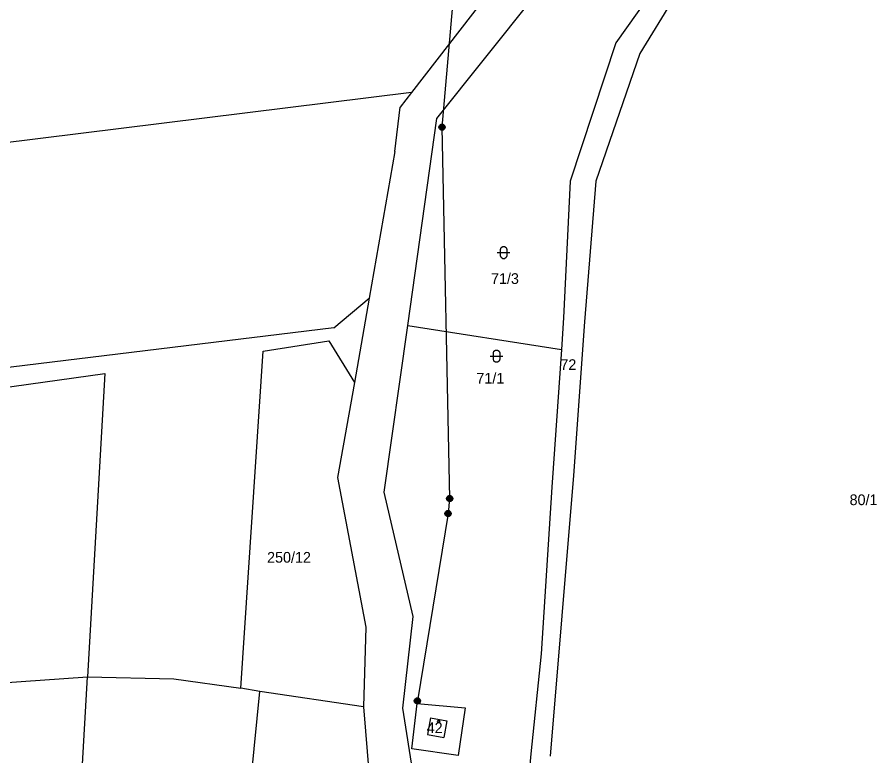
# Model space of a CAD drawing. Extents: x -852001 to -842497, y -1063614 to -1052182.
# Drawn here: x -844444 to -844307.7, y -1061323.1 to -1061205.9 of the extents above; entities that cross this region are included whole.
import ezdxf

# ---------------------------------------------------------------- set-up
doc = ezdxf.new("R2010")
doc.units = 0
for name, color, linetype in [('Default', 7, 'Continuous'), ('KN_HRANICE', 7, 'Continuous'), ('KN_KULTURY', 7, 'Continuous'), ('KN_PARCELY', 7, 'Continuous'), ('KN_SLUCKY', 7, 'Continuous'), ('KN_VEDENI', 7, 'Continuous')]:
    doc.layers.add(name, color=color, linetype=linetype)

# ---------------------------------------------------------------- blocks, each defined once
blk = doc.blocks.new('316')
at = {"layer": 'Default'}
for points in [[(-0.5, 1.5), (-0.4, 1.79), (-0.15, 1.97), (0.16, 1.97), (0.41, 1.79), (0.51, 1.5), (0.51, 0.5), (0.41, 0.21), (0.16, 0.03), (-0.15, 0.03), (-0.4, 0.21), (-0.5, 0.5), (-0.5, 1.5)], [(-1, 1), (0.27, 1), (1, 1)]]:
    blk.add_lwpolyline(points, dxfattribs=at)
blk = doc.blocks.new('402')
at = {"layer": 'Default'}
blk.add_lwpolyline([(0.09, 0.15), (0.18, 0), (0.09, -0.15), (-0.09, -0.15), (-0.18, 0), (-0.09, 0.15), (0.09, 0.15)], dxfattribs=at)
blk = doc.blocks.new('601')
at = {"layer": 'Default'}
blk.add_lwpolyline([(-0.15, 0.48), (0.16, 0.48), (0.41, 0.3), (0.51, 0.01), (0.41, -0.28), (0.16, -0.46), (-0.15, -0.46), (-0.4, -0.28), (-0.5, 0.01), (-0.4, 0.3), (-0.15, 0.48), (-0.12, 0.44), (0.12, 0.44), (0.28, 0.36), (-0.28, 0.36), (-0.36, 0.28), (0.36, 0.28), (0.36, 0.2), (-0.36, 0.2), (-0.4, 0.12), (0.4, 0.12), (0.44, 0.04), (-0.44, 0.04), (-0.44, -0.04), (0.44, -0.04), (0.41, -0.12), (-0.4, -0.12), (-0.39, -0.2), (0.42, -0.2), (0.37, -0.28), (-0.35, -0.28), (-0.27, -0.36), (0.29, -0.36), (0.18, -0.44), (-0.16, -0.44)], dxfattribs=at)

msp = doc.modelspace()

# ---------------------------------------------------------------- linework, layer by layer
at = {"layer": 'KN_HRANICE'}
for p, q in [((-844377.45, -1061221.98), (-844351.54, -1061189.47)), ((-844332.94, -1061191.52), (-844345.28, -1061211.64)), ((-844338.18, -1061194.58), (-844349.09, -1061209.93)), ((-844363.83, -1061194.99), (-844381.5, -1061217.84)), ((-844349.09, -1061209.93), (-844356.33, -1061231.92)), ((-844345.28, -1061211.64), (-844352.26, -1061231.88)), ((-844381.5, -1061217.84), (-844523.56, -1061235.4)), ((-844381.5, -1061217.84), (-844383.3, -1061220.16)), ((-844384.13, -1061227.2), (-844383.3, -1061220.16)), ((-844382.08, -1061254.79), (-844377.45, -1061221.98)), ((-844384.13, -1061227.2), (-844388.18, -1061250.45)), ((-844356.33, -1061231.92), (-844357.35, -1061253.58)), ((-844352.26, -1061231.88), (-844354.02, -1061254.23)), ((-844393.8, -1061255.17), (-844388.18, -1061250.45)), ((-844388.18, -1061250.45), (-844390.51, -1061263.85)), ((-844357.35, -1061253.58), (-844357.7, -1061258.58)), ((-844354.02, -1061254.23), (-844355.8, -1061278.6)), ((-844393.8, -1061255.17), (-844522.5, -1061270.83)), ((-844385.82, -1061281.23), (-844382.08, -1061254.79)), ((-844382.08, -1061254.79), (-844357.7, -1061258.58)), ((-844405.01, -1061258.87), (-844394.6, -1061257.22)), ((-844394.6, -1061257.22), (-844390.51, -1061263.85)), ((-844357.7, -1061258.58), (-844359.23, -1061280.44)), ((-844408.56, -1061312.3), (-844405.01, -1061258.87)), ((-844468.71, -1061267.83), (-844430.13, -1061262.42)), ((-844430.13, -1061262.42), (-844432.89, -1061310.51)), ((-844390.51, -1061263.85), (-844393.23, -1061278.9)), ((-844393.23, -1061278.9), (-844388.72, -1061302.67)), ((-844355.8, -1061278.6), (-844359.49, -1061323.11)), ((-844359.23, -1061280.44), (-844360.93, -1061306.9)), ((-844381.2, -1061300.98), (-844385.82, -1061281.23)), ((-844382.88, -1061315.51), (-844381.2, -1061300.98)), ((-844388.72, -1061302.67), (-844389.08, -1061315.26)), ((-844360.93, -1061306.9), (-844362.55, -1061322.76)), ((-844437.76, -1061395.7), (-844432.89, -1061310.51)), ((-844432.89, -1061310.51), (-844419.21, -1061310.86)), ((-844419.21, -1061310.86), (-844408.56, -1061312.3)), ((-844405.53, -1061312.84), (-844408.56, -1061312.3)), ((-844408.43, -1061341.94), (-844405.53, -1061312.84)), ((-844389.08, -1061315.26), (-844405.53, -1061312.84)), ((-844381.43, -1061321.93), (-844380.57, -1061314.74)), ((-844380.57, -1061314.74), (-844372.96, -1061315.44)), ((-844389.08, -1061315.26), (-844386.69, -1061344.57)), ((-844377.08, -1061352.12), (-844382.88, -1061315.51)), ((-844372.96, -1061315.44), (-844374.09, -1061323)), ((-844374.09, -1061323), (-844381.43, -1061321.93)), ((-844362.55, -1061322.76), (-844366.12, -1061360.65))]:
    msp.add_line(p, q, dxfattribs=at)
at = {"layer": 'KN_SLUCKY'}
for p, q in [((-844471.31, -1061313.26), (-844432.89, -1061310.51)), ((-844378.47, -1061317.03), (-844378.94, -1061319.66)), ((-844378.47, -1061317.03), (-844375.89, -1061317.52)), ((-844375.89, -1061317.52), (-844376.38, -1061320.13)), ((-844378.94, -1061319.66), (-844376.38, -1061320.13))]:
    msp.add_line(p, q, dxfattribs=at)
at = {"layer": 'KN_VEDENI'}
for p, q in [((-844371.23, -1061159.54), (-844376.65, -1061223.34)), ((-844376.65, -1061223.34), (-844375.44, -1061282.25)), ((-844375.44, -1061282.25), (-844375.69, -1061284.63)), ((-844375.69, -1061284.63), (-844380.55, -1061314.36))]:
    msp.add_line(p, q, dxfattribs=at)

# ---------------------------------------------------------------- block references
at = {"layer": 'KN_KULTURY'}
for name, p in [('316', (-844366.87, -1061244.23)), ('316', (-844368, -1061260.65)), ('402', (-844377.18, -1061317.63))]:
    msp.add_blockref(name, p, dxfattribs=at)
at = {"layer": 'KN_VEDENI'}
for p in [(-844376.65, -1061223.34), (-844375.44, -1061282.25), (-844375.69, -1061284.63), (-844380.55, -1061314.36)]:
    msp.add_blockref('601', p, dxfattribs=at)

# ---------------------------------------------------------------- texts
at = {"layer": 'KN_PARCELY'}
for s, p in [('71/3', (-844368.87, -1061248.2)), ('72', (-844357.87, -1061261.85)), ('71/1', (-844371.19, -1061264.01)), ('80/1', (-844311.98, -1061283.29)), ('250/12', (-844404.4, -1061292.42)), ('42', (-844379.08, -1061319.46))]:
    msp.add_text(s, height=1.7, dxfattribs=at).set_placement(p)

doc.saveas('drawing.dxf')
